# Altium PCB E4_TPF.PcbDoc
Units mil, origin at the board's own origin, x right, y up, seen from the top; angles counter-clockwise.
Board outline 7890 x 4000 mil, 2 copper layers (Top Layer, Bottom Layer); 83 components, 46 nets, 240 pads, 24 vias.
Unrouted connection lines stored in the file: 2.
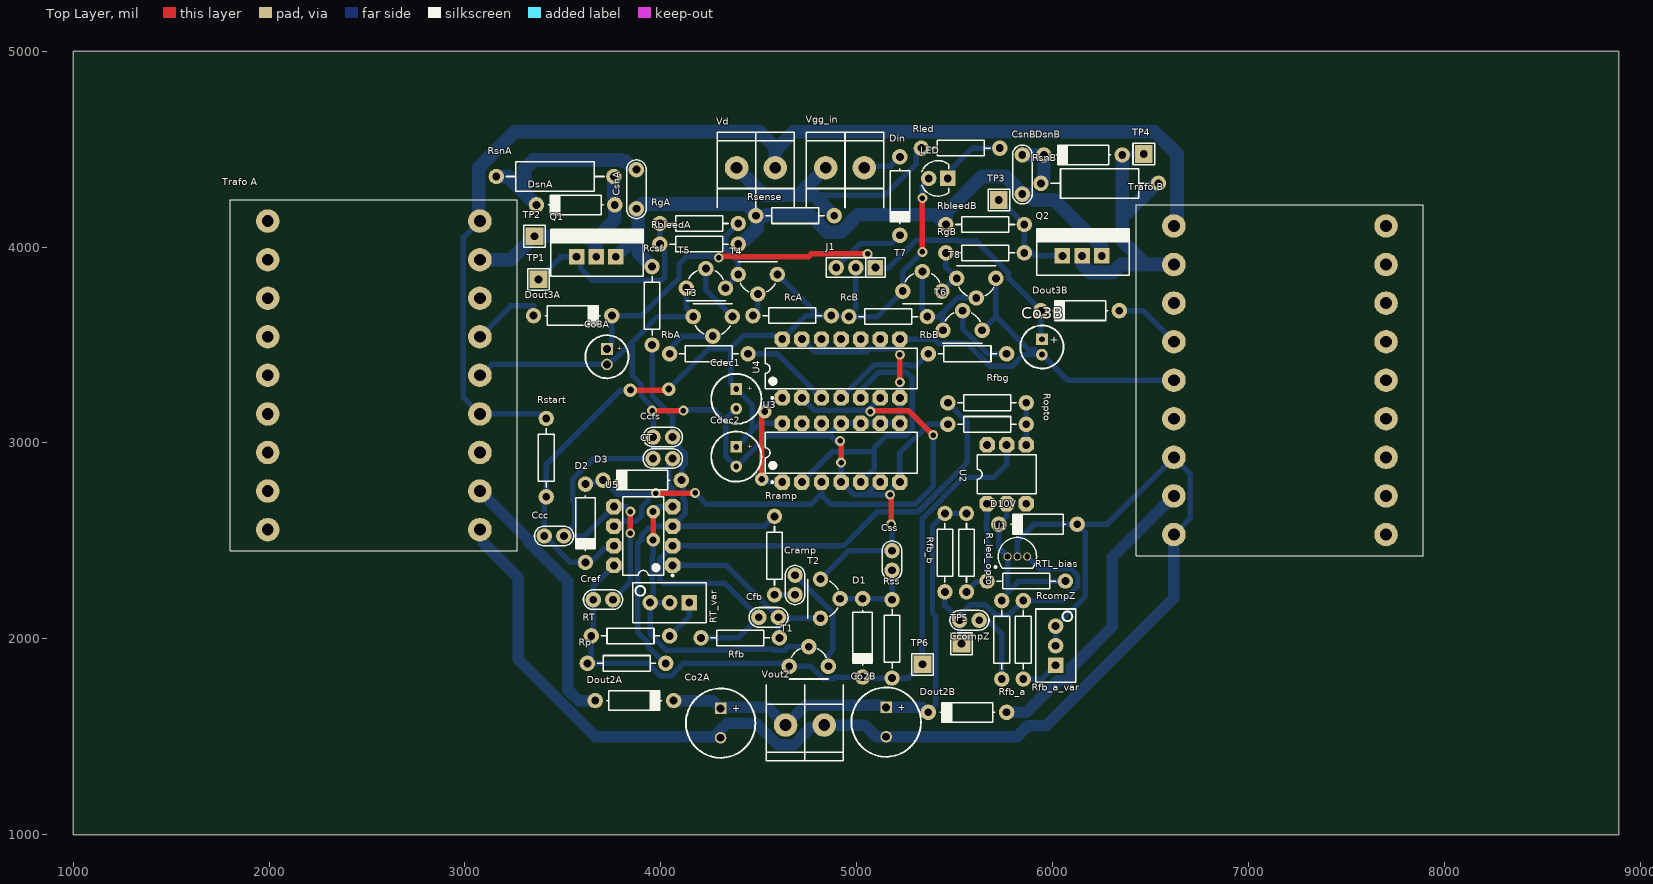
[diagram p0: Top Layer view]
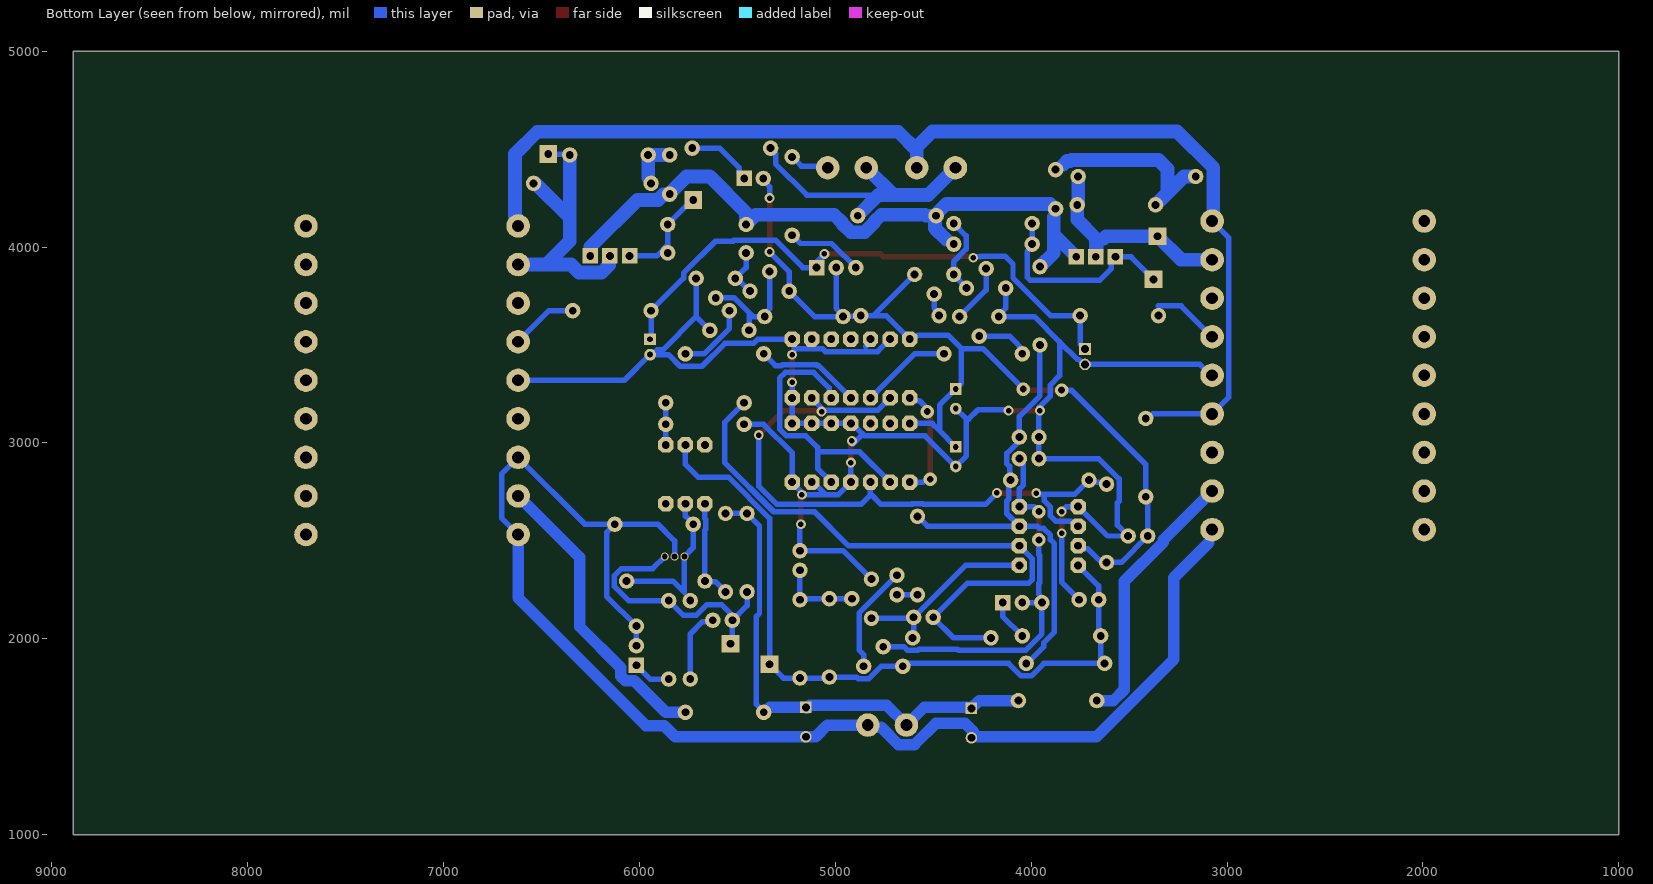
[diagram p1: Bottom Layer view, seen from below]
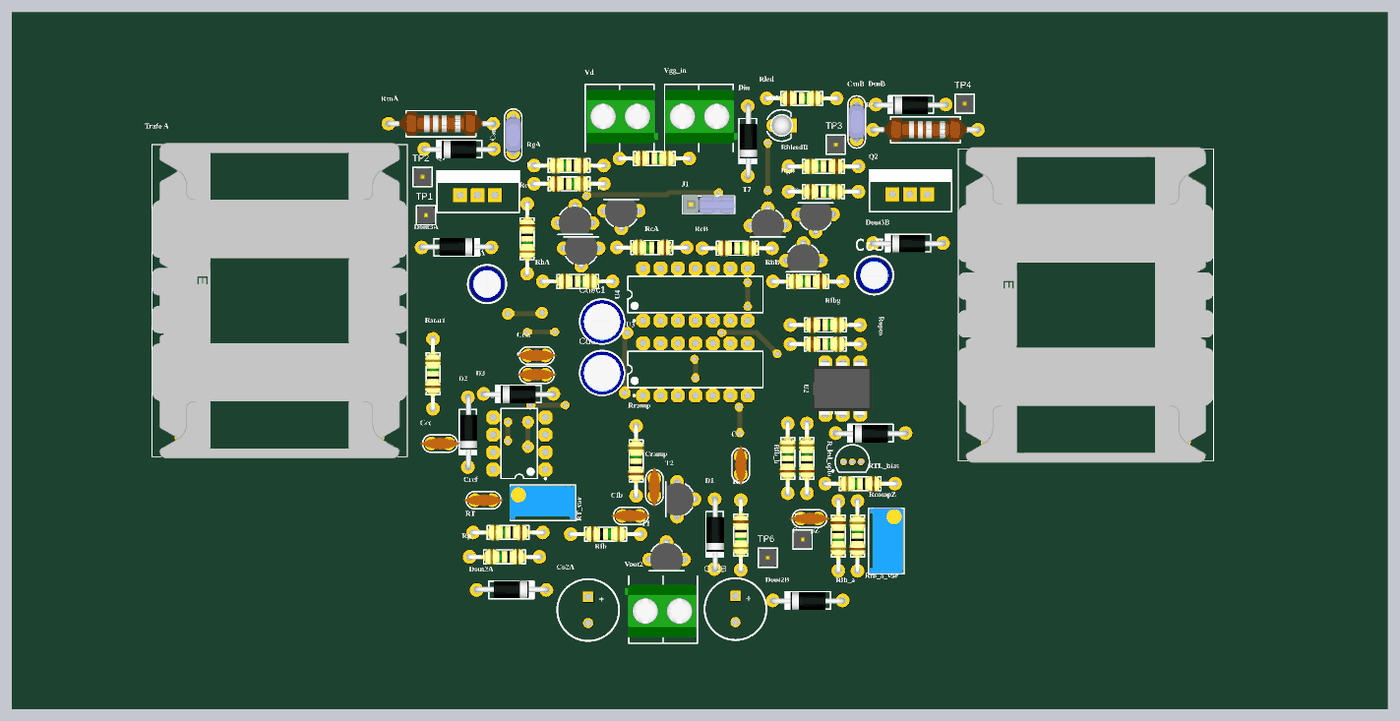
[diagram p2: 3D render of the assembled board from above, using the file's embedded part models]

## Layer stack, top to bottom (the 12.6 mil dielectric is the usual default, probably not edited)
Top Solder: solder mask 0.4, Solder Resist, Dk 3.5
Top Layer: signal copper 1.4
Dielectric 1: dielectric 12.6, FR-4, Dk 4.8
Bottom Layer: signal copper 1.4
Bottom Solder: solder mask 0.4, Solder Resist, Dk 3.5

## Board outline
1000,1000 8890,1000 8890,5000 1000,5000

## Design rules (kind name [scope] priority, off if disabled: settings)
Clearance [All] p1: gap=10 ignorepadtopadclearanceinfootprint=FALSE except(0: Arc-Hole Track-Hole SMDPad-Hole THPad-Hole Via-Hole Fill-Hole Poly-Hole Region-Hole Text-Hole)
PolygonConnect [All] p1: connectstyle=Relief reliefconductorwidth=10 reliefentries=4 polygonreliefangle="90 Angle" airgapwidth=10
RoutingVias [All] p1: holewidth=28 width=50 viastyle="Through Hole" minholewidth=28 minwidth=50 maxholewidth=28 maxwidth=50
SolderMaskExpansion [All] p1: expansion=4 istentingtop=FALSE
Width [All] p1: maxlimit=70 minlimit=28 preferedwidth=28
30 further rules are at their usual default settings.

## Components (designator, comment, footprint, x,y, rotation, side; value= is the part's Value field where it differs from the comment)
Ccc "100n" CAP100 3455,2525 r180 top
Ccfs "100p" CAP100 4010,3030 r0 top
CcompZ "100p" CAP100 5575,2095 r180 top
Cdec1 "10u" CAP100RP2 4385,3225 r270 top
Cdec2 "10u" CAP100RP2 4385,2930 r270 top
Cfb "100p" CAP100 4550,2110 r0 top
Co2A "100u" CAP300RP 4305,1570 r270 top
Co2B "100u" CAP300RP 5150,1575 r270 top
Co3A "1u" CAP100RP#1 3725,3440 r270 top
Co3B "1u" CAP100RP#2 5945,3490 r270 top
Cramp "1n" CAP100 4685,2275 r270 top
Cref "100n" CAP100 3705,2200 r180 top
CsnA "680p" CAP200 3875,4295 r90 top
CsnB "680p" CAP200 5845,4370 r90 top
Css "10u" CAP100 5180,2400 r270 top
CT "1.5n" CAP100 4010,2920 r0 top
D1 "1N4148" DO41 5030,2005 r270 top
D2 "1N5817" DO41 3615,2590 r270 top
D3 "1N5817" DO41 3905,2810 r180 top
D10V "BZX84C10L" DO41 5925,2585 r180 top
Din "1N4001" DO41 5220,4260 r270 top
Dout2A "MUR460" DO41 3865,1685 r0 top
Dout2B "MUR460" DO41 5565,1625 r180 top
Dout3A "MUR110" DO41 3550,3650 r0 top
Dout3B "MUR110" DO41 6140,3675 r180 top
DsnA "1N5819" DO41 3565,4215 r180 top
DsnB "1N5819" DO41 6155,4470 r180 top
J1 "JUMPER" JUMPER3 4995,3895 r180 top
LED "LED" LED3 5415,4350 r0 top
Q1 "IRF540" "TO-220 V" 3670,3950 r0 top
Q2 "IRF540" "TO-220 V" 6150,3955 r0 top
R_led_opto "15k" RES400 5560,2240 r90 top
RbA "1k" RES400 4045,3455 r0 top
RbB "1k" RES400 5765,3455 r180 top
RbleedA "10k" RES400 3995,4015 r0 top
RbleedB "10k" RES400 5855,4115 r180 top
RcA "560" RES400 4870,3650 r180 top
RcB "560" RES400 4960,3645 r0 top
RcompZ "88.7k" RES400 5740,2195 r270 top
Rcsf "1k" RES400 3955,3900 r270 top
Rfb "1.8k" RES400 4205,2005 r0 top
Rfb_a "1.8k" RES400 5850,1795 r90 top
Rfb_a_var "100" "PRESET V" 6015,1965 r90 top
Rfb_b "82k" RES400 5450,2240 r90 top
Rfbg "4.7k" RES400 5465,3205 r0 top
RgA "33" RES400 4395,4120 r180 top
RgB "33" RES400 5455,3970 r0 top
Rled "1.5k" RES400 5330,4505 r0 top
Ropto "1k" RES400 5465,3095 r0 top
Rp "12k" RES400 4025,1875 r180 top
Rramp "100k" RES400 4580,2225 r90 top
Rsense "0.1" RES400 4485,4160 r0 top
RsnA "220" RES600 3160,4360 r0 top
RsnB "220" RES600 5940,4325 r0 top
Rss "47k" RES400 5180,2200 r270 top
Rstart "100k" RES400 3415,2725 r90 top
RT "5.6k" RES400 4045,2015 r180 top
RT_var "5k" "PRESET V" 4045,2185 r180 top
RTL_bias "1k" RES400 6065,2295 r180 top
T1 "BC547B" TO92 4755,1910 r180 top
T2 "BC557B" TO92 4865,2205 r90 top
T3 "BC547B" TO92 4265,3595 r0 top
T4 "2N2222" TO92 4495,3810 r0 top
T5 "2N2905A" TO92 4230,3840 r180 top
T6 "BC547B" TO92 5540,3625 r180 top
T7 "2N2222" TO92 5335,3825 r180 top
T8 "2N2905A" TO92 5610,3790 r0 top
TP1 "TP" TPTH 3375,3835 r0 top
TP2 "TP" TPTH 3355,4055 r0 top
TP3 "TP" TPTH 5725,4240 r270 top
TP4 "TP" TPTH 6465,4475 r0 top
TP5 "TP" TPTH 5535,1975 r0 top
TP6 "TP" TPTH 5335,1870 r0 top
"Trafo A" "B66243B1018T001" B66243B1018T001 2535,3345 r270 top
"Trafo B" "B66243B1018T001" B66243B1018T001 7160,3320 r270 top
U1 "TL431ACZ" TO-92 5820,2420 r270 top
U2 "4N25" DIP6 5665,2690 r90 top
U3 "CD4013BE" N0014A 4920,2950 r90 top
U4 "CD4011BE" N0014A 4920,3380 r90 top
U5 "UC3843AN" P0008A 3910,2525 r180 top
Vd "BORNERA 2" BORNERA2 4485,4405 r270 top
Vgg_in "BORNERA 2" BORNERA2 4940,4405 r270 top
Vout2 "BORNERA 2" BORNERA2 4735,1560 r90 top

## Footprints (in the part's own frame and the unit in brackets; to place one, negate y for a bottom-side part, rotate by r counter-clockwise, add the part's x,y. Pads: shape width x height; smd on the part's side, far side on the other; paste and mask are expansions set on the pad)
B66243B1018T001 [mil]
  round 120 hole 60: 1(-787.4,-541.34) 2(-787.4,541.34) 3(-590.55,-541.34) 4(-590.55,541.34) 5(-393.7,-541.34) 6(-393.7,541.34) 7(-196.85,-541.34) 8(-196.85,541.34) 9(0,-541.34) 10(0,541.34) 11(196.85,-541.34) 12(196.85,541.34) 13(393.7,-541.34) 14(393.7,541.34) 15(590.55,-541.34) 16(590.55,541.34) 17(787.4,-541.34) 18(787.4,541.34)
  silkscreen extent -896,-732 896,732, body extent -906,-732 906,732, height 1795
BORNERA2 [mil] "Bornera con Tornillos 5mm separación"
  round 120 hole 60: 1(0,98.43) 2(0,-98.43)
  silkscreen extent -181,-197 205,197, body extent -148,-193 155,221, height 394
CAP100 [mil]
  oval 79.06x79 hole 40: 1(-50,0) 2(50,0)
  silkscreen extent -100,-50 100,50, body extent -115,-33 115,34, height 241
CAP100RP#1 [mil] "Body diameter 5mm"
  rect 59x59 hole 40: 1(-39.37,0)
  round 59 hole 40: 2(39.37,0)
  silkscreen extent -110,-110 110,110, body extent -99,-99 99,100, height 454
CAP100RP#2 [mil] "Body diameter 5mm"
  rect 60x60 hole 30: 1(-39.37,0)
  round 60 hole 30: 2(39.37,0)
  silkscreen extent -110,-110 110,110, body extent -99,-99 99,100, height 454
CAP100RP2 [mil] "Body diameter 6.5mm"
  rect 60x60 hole 30: 1(-50,0)
  round 60 hole 30: 2(50,0)
  silkscreen extent -128,-128 128,128, body extent -124,-125 126,125, height 454
CAP200 [mil]
  oval 79.06x79 hole 40: 1(-100,0) 2(100,0)
  silkscreen extent -150,-50 150,50, body extent -110,-46 110,44, height 246
CAP300RP [mm]
  rect 1.5x1.5 hole 1.016: 1(-1.905,0)
  round 1.5 hole 1.016: 2(1.905,0)
  silkscreen extent -4.5,-4.5 4.5,4.5
DIP6 [mil]
  oct 79.06x79 hole 40: 1(0,0) 2(0,-100) 3(0,-200) 4(300,-200) 5(300,-100) 6(300,0)
  silkscreen extent 50,-250 250,50, body extent -5,-269 305,77, height 209
DO41 [mil]
  oval 79.06x79 hole 40: 1(-200,0) 2(200,0)
  silkscreen extent -140,-50 140,50, body extent -215,-47 215,54, height 80
JUMPER3 [mil]
  rect 79.06x79 hole 40: 1(-100,0)
  oval 79.06x79 hole 40: 2(0,0) 3(100,0)
  silkscreen extent -150,-50 150,50, body extent -150,-51 150,50, height 636
LED3 [mil]
  oval 79.06x79 hole 40: 1(-48,0)
  rect 79.06x79 hole 40: 2(49,0)
  silkscreen extent -84,-90 54,90, body extent -65,-64 65,65, height 19
N0014A [mil] "DIP, 14-Leads, Body 19.7x6.6mm, Pitch 2.54mm"
  oct 79.06x79 hole 40: 1(-150,300) 2(-150,200) 3(-150,100) 4(-150,0) 5(-150,-100) 6(-150,-200) 7(-150,-300) 8(150,-300) 9(150,-200) 10(150,-100) 11(150,0) 12(150,100) 13(150,200) 14(150,300)
  silkscreen extent -155,-388 104,388, body extent -155,-388 155,388, height 200
P0008A [mil] "DIP, 8-Leads, Body 10.15x6.6mm, Pitch 2.54mm"
  oct 79.06x79 hole 40: 1(-150,150) 2(-150,50) 3(-150,-50) 4(-150,-150) 5(150,-150) 6(150,-50) 7(150,50) 8(150,150)
  silkscreen extent -155,-201 104,206, body extent -155,-200 155,200, height 200
"PRESET V" [mil]
  rect 79.06x79 hole 40: 1(-100,0)
  oval 79.06x79 hole 40: 2(0,0) 3(100,0)
  silkscreen extent -188,-102 188,102, body extent -185,-95 190,95, height 455
RES400 [mil]
  oval 79.06x79 hole 40: 1(0,0) 2(400,0)
  silkscreen extent 50,-40 350,40, body extent -12,-45 412,46, height 96
RES600 [mil]
  oval 79.06x79 hole 40: 1(0,0) 2(600,0)
  silkscreen extent 50,-75 550,75, body extent -16,-68 616,70, height 141
TO92 [mil]
  oval 79.06x79 hole 40: 1(0,-50) 2(100,50) 3(-100,50)
  silkscreen extent -100,-39 100,115, body extent -110,-61 110,110, height 315
TO-92 [mil] "TO, Flat Index; 3 In-Line, Axial Leads; Body Dia. 4.7mm; Lead Dia. 0.56 mm (max)"
  round 41 hole 30: 1(0,-50) 2(0,0) 3(0,50)
  silkscreen extent -98,-116 59,98, body extent -98,-98 59,98, height 195
"TO-220 V" [mil]
  rect 79.06x79 hole 40: 1(-100,0) 2(0,0) 3(100,0)
  silkscreen extent -232,-100 240,139, body extent -197,-79 197,118, height 709
TPTH [mm]
  rect 2.3x2.3 hole 1.016: 1(0,0)
  silkscreen extent -1.4,-1.4 1.4,1.4, body extent -1.27,-1.27 1.27,1.27, height 6.04

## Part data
Ccc Ccfs CcompZ Cfb Cramp Cref CsnA CsnB Css CT: library part CAP
Cdec1 Cdec2 Co2A Co2B Co3A Co3B: library part CAPPOL
D1 Din Dout2A Dout2B Dout3A Dout3B: library part DIODO
D2 D3 D10V: library part "DIODO ZENER"
DsnA DsnB: library part "DIODO SCHOTTKY"
J1: library part JUMPER3
Q1 Q2: library part "MOSFET N"
R_led_opto RbA RbB RbleedA RbleedB RcA RcB RcompZ Rcsf Rfb Rfb_a Rfb_b Rfbg RgA RgB Rled Ropto Rp Rramp Rsense RsnA RsnB Rss Rstart RT RTL_bias: library part RES
Rfb_a_var RT_var: library part PRESET
T1 T3 T4 T6 T7: library part "TRANSISTOR NPN"
T2 T5 T8: library part "TRANSISTOR PNP"
"Trafo A" "Trafo B": "Inductor", Manufacturer_Name=TDK, Mouser Part Number=N/A
U1: library part CMP-0242-00006-1, "Programmable Voltage Reference, 2.5 to 36V, 3-Pin TO-92"
U3: library part CMP-1619-00744-2, "CMOS Dual D-Type Flip Flop, N0014A, TUBE", F @ Nom Voltage(Max)(Mhz)=8, Generic Part Number=CD4013B, ICC @ Nom Voltage(Max)(mA)=0.06, Manufacturer="Texas Instruments", Operating Temperature Range(C)="-55 to 125", Rating=Military, tpd @ Nom Voltage(Max)(ns)=130, Voltage(Nom)(V)=10
U4: library part CMP-1627-00488-2, "CMOS Quad 2-Input NAND Gate, N0014A, TUBE", F @ Nom Voltage(Max)(Mhz)=8, Generic Part Number=CD4011B, ICC @ Nom Voltage(Max)(mA)=0.015, Manufacturer="Texas Instruments", Operating Temperature Range(C)="-55 to 125", Rating=Military, Voltage(Nom)(V)=10
U5: library part CMP-0319-00327-2, "PWM Controller with Current Control, 100 % Duty Cycle, 0 to +70 degC, 8-pin PDIP (P), Green (RoHS & no Sb/Br)", Frequency(Max)(kHz)=450, Manufacturer="Texas Instruments", Rating=Catalog

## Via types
v1: diameter 50, hole 28, Top Layer to Bottom Layer, 18 vias
v2: diameter 69, hole 35, Top Layer to Bottom Layer, 6 vias

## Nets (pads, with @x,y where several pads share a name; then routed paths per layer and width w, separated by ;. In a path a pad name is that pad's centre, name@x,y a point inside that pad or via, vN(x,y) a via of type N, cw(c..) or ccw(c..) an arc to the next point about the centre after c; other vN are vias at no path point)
-Q: U3.2 U3.5 U4.5 | length 1486.3
  Bottom Layer w28: U3.2 4875,2955 5090.31,2955 ; U3.5 5090.31,2870.31 5090.31,2955 ; U4.5 5031.34,3241.34 5031.34,3281.34 5110,3360 5255,3360 5283.5,3331.5 5283.5,3070.28 5249.69,3036.47 5149.69,3036.47 5090.31,2977.09 5090.31,2955
GND: "Trafo A.10" "Trafo B.9" Ccc.1 Ccfs.1 Cdec1.2 Cdec2.2 Co3A.2 Co3B.2 Cref.1 Css.1 CT.1 Rled.1 Ropto.1 Rsense.2 T2.2 T3.3 T5.2 T6.3 T8.2 U3.4 U3.6 U3.7 U3.8 U3.9 U3.10 U3.11 U4.7 U4.8 U4.9 U4.12 U4.13 U5.5 Vd.2 Vgg_in.2 | length 11891.7
  Top Layer w28: v1(3844.24,2539.24) 3844.24,2649.24 v1(3845,2650) ; v1(3955,3165) v1(4115,3165) ; v1(4915,3010) 4915,3004.05 4920,2999.05 v1(4920,2900) ; v1(5170,2735.77) 5170,2729.82 5175,2724.82 v1(5175,2585) ; v1(5220,3310) v1(5220,3450)
  Bottom Layer w28: 3076.34,3345 3083.11,3345 3138.74,3400.63 Co3A.2 3731.66,3400.63 3756.9,3425.87 3764.44,3425.87 3854.29,3515.71 ; Cref.1 3843.47,2288.47 3843.47,2538.47 v1(3844.24,2539.24) v1@3845,2540 ; v1(3845,2650) 3821.34,2673.66 3761.34,2673.66 U5.5 3610,2525 Ccc.1 3560,2580 3560,2693.91 3551.5,2702.41 3551.5,2816.33 3655.17,2920 CT.1 Ccfs.1 3960,3181.26 3903.5,3237.76 3903.5,3294.23 3854.29,3343.45 3854.29,3515.71 ; v1@4114.67,3170 4115.46,3169.21 4134.77,3169.21 4135.56,3170 4270,3170 4319,3121 4331,3121 ; T5.2 4130,3686.9 4165,3651.9 T3.3 3983.57,3645 3854.29,3515.71 ; Cdec1.2 4331,3121 ; 4510,4281.4 4510,4281.57 ; U4.13 4783.53,3466.47 5049.69,3466.47 5063.22,3480 5120,3480 ; 4780,4265 5015,4265 5144.53,4265 5304.5,4424.97 Rled.1@5304.5,4477.09 ; T2.2 4960,2450 Css.1 v1@5180,2595 ; U4.12 4820,3518.42 4843.84,3494.59 4843.84,3491.16 4845,3490 ; 4859.11,3045.89 v1@4912,2993 ; v1(4920,2900) U3.4 4983.53,2736.47 5049.69,2736.47 ; U3.6 5113.22,2800 5049.69,2736.47 ; U4.9 5120,3480 ; v1@5220,3300 U4.7 U3.8 U3.9 U3.10 U3.11 4913.22,3100 4849.69,3036.47 4541.47,3036.47 Cdec2.2 4331,2934 4331,3121 ; v1@5220,3460 5208.6,3471.4 5208.6,3480 ; Rled.1@5325.4,4505 Rled.1 ; Ropto.1 5365,3095 5220,2950 U3.7 5220,2797.07 5174.21,2751.28 5174.21,2739.98 v1(5170,2735.77) 5169.3,2736.47 5049.69,2736.47 ; T6.3 5710,3645 ; T8.2 5710,3645 ; 6618.66,3320 6075.63,3320 Co3B.2 Co3B.2@5936.34,3450.63 ; 5120,3480 5208.6,3480 ; 5208.6,3480 5208.6,3518.6 U4.8 5395.17,3530 5416.96,3508.21 5563.21,3508.21 5679.93,3391.5 5791.33,3391.5 5850.46,3450.63 Co3B.2@5936.34,3450.63 ; 5710,3645 5879.63,3475.37 5909.63,3475.37 5918.37,3466.63 5920.34,3466.63 Co3B.2@5936.34,3450.63
  Bottom Layer w70: Vd.2 4510,4281.57 ; 4510,4281.4 4526.4,4265 4701.57,4265 ; Vgg_in.2 4701.57,4265 ; Rsense.2 4780,4265 4701.57,4265 ; Rled.1@5330,4502.59 Rled.1
GND_OUT: "Trafo A.18" "Trafo B.13" "Trafo B.17" Co2A.2 Co2B.2 D10V.1 Rfb_a_var.2 Rfb_a_var.3 U1.2 Vout2.2 | length 7267
  Bottom Layer w28: 3076.34,2557.6 3093.94,2539.99 3093.94,2491.06 ; Co2B.2 5155.94,1505.94 5165,1505.94 5180.94,1505.94 ; U1.2 5820,2500 5905,2585 D10V.1 ; Rfb_a_var.2 Rfb_a_var.3 6166.53,2216.53 6166.53,2543.1 6125,2584.63 D10V.1 ; 6618.66,2532.6 6702.66,2616.6 6702.66,2842.3 6618.66,2926.3 6277.36,2585 D10V.1
  Bottom Layer w59: 3093.94,2491.06 3272.5,2312.5 3272.5,1894.92 3666.45,1500.97 4275.89,1500.97 4287.46,1512.54 4299.03,1524.11 4299.03,1531.45 4337.57,1569.99 4379.99,1569.99 4485.86,1570 4595.36,1460.5 4677.79,1460.5 4765.62,1548.33 4821.75,1548.33 Vout2.2 5040,1560 5099.99,1500.01 Co2B.2 5180.94,1500 5816.71,1500 5872.71,1556 5966,1556 6618.66,2208.66 6618.66,2532.6
NetCcfs_2: Ccfs.2 D3.1 Rcsf.2 Rp.1 Rramp.2 U5.3 | length 2478.1
  Bottom Layer w28: Rcsf.2 3955,3240 4060,3135 Ccfs.2 4069.79,3020.21 4069.79,3000.04 4123.53,2946.3 4123.53,2893.7 4110,2880.17 4110,2815 D3.1 4114.79,2800.21 4114.79,2768.31 4115,2768.1 4115,2713.22 4123.53,2704.69 4123.53,2638.53 U5.3 ; Rp.1@4022.5,1872.5 3935,1960 3935,1981.43 3881.47,2034.96 3881.47,2486.47 3901.5,2506.5 3901.5,2529.23 3935.77,2563.5 3958.5,2563.5 3970,2575 U5.3 ; Rramp.2 4530,2575 U5.3
NetCcompZ_1: CcompZ.1 RcompZ.2 | length 374
  Bottom Layer w28: CcompZ.1 5632.14,2087.86 5677.14,2087.86 5740,2025 RcompZ.2
NetCcompZ_2: CcompZ.2 Rfb_a.2 Rfb_b.1 TP5.1 U1.3 | length 1387.9
  Bottom Layer w28: Rfb_b.1 5450,2170 CcompZ.2 ; TP5.1 5525,1985 CcompZ.2 ; U1.3 5931.5,2358.5 6091.33,2358.5 6128.53,2321.3 6128.53,2268.7 6054.83,2195 Rfb_a.2 5775,2120 5710,2120 5655,2175 5580,2175 5534.79,2129.79 5534.79,2104.79 CcompZ.2
NetCfb_2: Cfb.2 Rfb.2 T2.3 U5.1 | length 973.9
  Bottom Layer w28: U5.1 4335,2375 Cfb.2 ; Rfb.2 4600,2010 Cfb.2 ; T2.3 4605,2105 Cfb.2
NetCramp_1: Cramp.1 T1.3 | length 554.9
  Bottom Layer w28: Cramp.1 4878.5,2131.5 4878.5,1943.5 4855,1920 T1.3
NetCramp_2: Cramp.2 Rramp.1 | length 105
  Bottom Layer w28: Rramp.1 Cramp.2
NetCsnA_2: CsnA.2 DsnA.2 RsnA.1 | length 997.8
  Bottom Layer w28: 3817.33,4438.9 3820.83,4435.4 ; 3836.23,4420 3861.23,4395 CsnA.2
  Bottom Layer w70: RsnA.1 3220,4360 3303.77,4276.23 ; DsnA.2 3303.77,4276.23 ; 3817.33,4438.9 3800.63,4438.9 3795.03,4444.5 3350.38,4444.5 3303.77,4397.89 3303.77,4276.23 ; 3820.83,4435.4 3836.23,4420
NetCsnB_2: CsnB.2 DsnB.2 RsnB.1 | length 272.9
  Bottom Layer w28: CsnB.2@5836.73,4461.73 CsnB.2 ; RsnB.1 5940,4338.77 RsnB.1@5955,4353.77
  Bottom Layer w70: CsnB.2 DsnB.2 RsnB.1@5955,4353.77
NetCss_2: Css.2 D1.1 Rss.1 T2.1 | length 417.1
  Bottom Layer w28: T2.1 D1.1 5175,2205 Rss.1 Css.2
NetCT_2: CT.2 RT_var.2 RT_var.3 T1.1 U5.4 | length 1961.6
  Top Layer w28: v2(3960,2505) v2(3960,2650)
  Bottom Layer w28: v2(3960,2505) 3960,2428.74 3957,2425.74 3957,2285.66 3960,2282.66 3960,2226.9 3954.79,2221.69 3954.79,2194.79 RT_var.3 ; v2(3960,2650) 3985,2675 U5.4 4060,2765.17 4041.47,2783.7 4041.47,2887.7 4060,2906.23 CT.2 ; RT_var.2 RT_var.3 ; T1.1 4649.83,1960 4631.33,1941.5 4578.67,1941.5 4572.53,1947.64 4376.09,1947.64 4369.94,1941.5 4028.67,1941.5 3945,2025.17 RT_var.3
NetD10V_2: D10V.2 RcompZ.1 RTL_bias.1 U1.1 U2.2 | length 807.3
  Bottom Layer w28: U2.2 5765,2626.9 5725,2586.9 D10V.2 5725,2465 U1.1 5770,2236.93 5828.07,2295 RTL_bias.1
NetDin_1: Din.1 Vgg_in.1 | length 205.3
  Bottom Layer w28: Vgg_in.1 5046.76,4413.34 5173.34,4413.34 Din.1@5220.68,4460.68
NetDin_2: Din.2 J1.3 | length 421.2
  Bottom Layer w28: J1.3@4887.32,3887.32 5018,4018 5178,4018 Din.2 5220,4069.93 Din.2@5215.04,4064.96
NetDout2A_1: "Trafo A.16" Dout2A.1 | length 1363.1
  Bottom Layer w59: 3076.34,2754.45 3325.97,2504.81 3325.97,2492.28 3525,2293.25 3525,1740 3580,1685 Dout2A.1
NetDout2B_1: "Trafo B.15" Dout2B.1 | length 1542.9
  Bottom Layer w59: Dout2B.1 5865,1625 6025.97,1785.97 6070.86,1785.97 6094,1809.11 6094,1851.71 6305,2062.71 6305,2415.79 6618.66,2729.45
NetDout3A_1: "Trafo A.8" Dout3A.1 | length 339.2
  Bottom Layer w28: 3076.34,3541.85 3234.49,3700 3350,3700
NetDout3B_1: "Trafo B.7" Dout3B.1 | length 344.2
  Bottom Layer w28: Dout3B.1 6460.51,3675 6618.66,3516.85
NetDsnA_1: "Trafo A.4" DsnA.1 Q1.2 RsnA.2 TP2.1 | length 1153.7
  Bottom Layer w28: 3630,4042.46 3644.47,4027.99 Q1.2@3644.47,3975.5 ; DsnA.1@3760,4220 DsnA.1
  Bottom Layer w70: 3076.34,3935.55 3235.55,3935.55 TP2.1 3617.46,4055 3630,4042.46 ; Q1.2 Q1.2@3670,3975.5 ; Q1.2@3670,3954.5 3670,4045 3765,4140 DsnA.1 ; DsnA.1@3760,4220 RsnA.2
NetDsnB_1: "Trafo B.3" DsnB.1 Q2.2 RsnB.2 TP4.1 | length 1538.1
  Bottom Layer w28: DsnB.1 6358.04,4473.04 6463.04,4473.04 TP4.1 TP4.1@6455,4485 ; RsnB.2@6530,4325 RsnB.2
  Bottom Layer w70: Q2.2 6154.53,3950.5 6154.53,3907.81 6191.83,3870.5 6308.17,3870.5 6348.22,3910.55 6475,3910.55 ; DsnB.1 6355,4150 ; RsnB.2@6530,4325 6355,4150 ; 6618.66,3910.55 6475,3910.55 ; 6355,4150 6355,4030.55 6475,3910.55
NetLED_2: LED.2 Rled.2 | length 347.2
  Bottom Layer w28: LED.2 5489.53,4375.5 5489.53,4404.53 5590,4505 Rled.2
NetQ1_1: Q1.1 RbleedA.1 RgA.2 TP1.1 | length 1056.5
  Bottom Layer w28: TP1.1 3490,3950 Q1.1 3591.21,3928.79 3591.21,3888.79 3650,3830 4003.6,3830 4020,3846.4 4020,3976.23 3995,4001.23 RgA.2
NetQ2_1: Q2.1 RbleedB.1 RgB.2 TP3.1 | length 518.3
  Bottom Layer w28: TP3.1 5756.28,4208.72 5761.28,4208.72 RbleedB.1 5855,4010 5910,3955 Q2.1 ; RgB.2@5855,3956.23 RgB.2
NetR_led_opto_1: R_led_opto.1 RTL_bias.2 U2.1 | length 525.7
  Bottom Layer w28: R_led_opto.1 5611.73,2291.73 5661.73,2291.73 RTL_bias.2 5665,2555.17 5661.47,2558.7 5661.47,2611.3 5665,2614.83 U2.1
NetRbA_1: RbA.1 T3.1 | length 282.3
  Bottom Layer w28: RbA.1@4020,3455 4110,3545 T3.1
NetRbA_2: RbA.2 U4.3 | length 493.2
  Bottom Layer w28: RbA.2@4420,3455 4595,3455 U4.3
NetRbB_1: RbB.1 T6.1 | length 368.7
  Bottom Layer w28: T6.1 5540,3585.17 5670.17,3455 RbB.1
NetRbB_2: RbB.2 U4.4 | length 540.7
  Bottom Layer w28: U4.4 5085,3395 5091.26,3395 5094.26,3398 5270.74,3398 5273.74,3395 5305,3395 RbB.2
NetRcA_2: RcA.2 T3.2 T4.1 T5.1 | length 421.3
  Bottom Layer w28: T5.1 4230,3780 T3.2 ; RcA.2 4470,3663.77 4495,3688.77 T4.1
NetRcB_2: RcB.2 T6.2 T7.1 T8.1 | length 619.5
  Bottom Layer w28: T7.1 5335,3683.77 5360,3658.77 RcB.2 5420.17,3645 5440,3664.83 ; T6.2 5440,3664.83 ; T8.1 5515.17,3740 5440,3664.83
NetRfb_a_1: Rfb_a.1 Rfb_a_var.1 | length 194
  Bottom Layer w28: Rfb_a.1 5945,1795 Rfb_a_var.1@5989.47,1839.47 ; Rfb_a_var.1@5989.5,1839.47 Rfb_a_var.1
NetRfbg_2: Rfbg.2 Ropto.2 U2.4 | length 215
  Bottom Layer w28: U2.4 Ropto.2 Rfbg.2
NetRT_1: RT.1 RT_var.1 | length 211.4
  Bottom Layer w28: RT.1 4145,2115 RT_var.1
Q: U3.1 U4.1 | length 594.1
  Top Layer w28: v2(4515,2815) 4515,3139.05 4530,3154.05 v2(4530,3160)
  Bottom Layer w28: v2@4515,2835 4550,2800 U3.1 ; v2@4522.5,3167.5 4571.16,3216.16 4606.16,3216.16 U4.1
Vcontrol: D2.1 D3.2 U3.3 U4.2 U4.6 U5.6 | length 3336.9
  Top Layer w28: v1(3974.25,2744.25) 4174.25,2744.25 v1(4175,2745) ; v1(5070,3160) 5073.53,3163.53 5266.47,3163.53 v1(5390,3040)
  Bottom Layer w28: D2.1@3640,2790 3649.79,2799.79 3680.96,2799.79 3691.17,2810 D3.2 3776.5,2738.5 3921.5,2738.5 ; U5.6 3771.58,2575 3797.58,2601 3874.6,2601 3901.5,2627.9 3901.5,2674.23 3932.04,2704.77 3932.04,2727.96 3921.5,2738.5 ; v1(3974.25,2744.25) 3968.5,2738.5 3921.5,2738.5 ; v1(4175,2745) 4233.23,2686.77 4551.94,2686.77 4553.7,2688.53 4606.3,2688.53 4608.06,2686.77 4766.77,2686.77 4818.66,2738.66 ; U4.2 4783.53,3166.47 5056.47,3166.47 U4.6 ; U3.3 4820,2735 4868.23,2686.77 5298.03,2686.77 5390,2778.74 v1(5390,3040)
Vd: "Trafo A.2" "Trafo A.12" "Trafo B.1" Rstart.2 Vd.1 | length 5918.7
  Bottom Layer w28: 3076.34,4132.4 2992.34,4048.4 2992.34,3232.15 3076.34,3148.15 3378.08,3148.15 3401.23,3125 Rstart.2 ; 4583.43,4493.43 4583.43,4511.57
  Bottom Layer w70: 3076.34,4132.4 3070,4138.74 3070,4405 3255,4590 4505,4590 4583.43,4511.57 ; Vd.1 4583.43,4493.43 4678.52,4588.53 6521.3,4588.53 6635,4474.83 6635,4159.1 6628.23,4152.32 6628.23,4116.97 6618.66,4107.4
VgA: RgA.1 T4.3 T5.3 | length 409.6
  Bottom Layer w28: T5.3 4330,3792.43 4395,3857.43 T4.3 4395,3925.17 4331.47,3988.7 4331.47,4056.47 RgA.1
VgB: RgB.1 T7.3 T8.3 | length 254.7
  Bottom Layer w28: T7.3 5437.43,3775 5502.43,3840 T8.3 5455,3895 RgB.1
Vgg: Ccc.2 Cdec1.1 Cdec2.1 D2.2 J1.2 LED.1 RcA.1 RcB.1 Rstart.1 T4.2 T7.2 U3.14 U4.14 U5.7 | length 4968.8
  Top Layer w28: v2(3845,3270) 4035,3270 v2(4040,3275) ; v1(5335,3975) v1(5335,4250)
  Bottom Layer w28: Rstart.1@3405,2739.82 3405.24,2739.58 3405.24,2701.41 3405,2701.17 Ccc.2 3540,2390 D2.2 ; Rstart.1 3415,2890 3793.91,3268.91 3843.91,3268.91 v2(3845,3270) ; D2.2@3640,2390 3711.16,2461.16 3746.16,2461.16 U5.7 ; v2@4025,3275 v2(4040,3275) 4246.3,3481.3 4356.47,3481.3 ; Cdec2.1 4467.5,3062.5 ; T4.2 4805,3650 ; U3.14 4505,3100 4467.5,3062.5 ; J1.2@4995,3899.72 4995,3686.9 4960,3651.9 RcB.1 ; v1(5335,3975) 5235,3875 T7.2 5105,3645 RcB.1 ; v1(5335,4250) 5335,4308.1 5367,4340.1 LED.1 ; 4356.47,3481.3 4356.47,3303.53 Cdec1.1 4467.5,3192.5 4467.5,3062.5 ; 4356.47,3481.3 4425.17,3550 4578.1,3550 4584.12,3543.98 4606.02,3543.98 U4.14 4740,3650 4805,3650 ; 4805,3650 RcA.1 4872.5,3647.5 4957.5,3647.5 RcB.1
Vo2: Co2A.1 Co2B.1 Dout2A.2 Dout2B.2 R_led_opto.2 Rfb_b.2 Vout2.1 | length 2583.9
  Bottom Layer w28: Dout2B.2 5365,1627.63 5404.28,1666.9 5404.28,2112.81 5386.5,2130.59 5386.5,2576.5 Rfb_b.2 R_led_opto.2
  Bottom Layer w59: Dout2A.2 4265,1685 Co2A.1 ; Co2A.1 Co2A.1 4322.36,1645.03 4327.34,1650 4546.57,1650 Vout2.1 4736.57,1660 5130,1660 Co2B.1@5145,1645 ; Co2B.1 5334.56,1650 5359.56,1625 Dout2B.2
Vo3: Co3A.1 Co3B.1 Dout3A.2 Dout3B.2 J1.1 | length 3010.3
  Top Layer w28: v1(4295,3945) 4299.21,3949.21 4314.77,3949.21 4319.06,3953.5 4366.67,3953.5 4368.67,3951.5 4755,3951.5 4768.5,3965 v1(5055,3965)
  Bottom Layer w28: Co3A.1 3750,3504.37 Dout3A.2 3900.17,3650 4092.59,3842.41 4092.59,3912.6 4133.49,3953.5 4256.33,3953.5 4260.62,3949.21 4290.79,3949.21 v1(4295,3945) ; v1(5055,3965) 5055,3959.05 5069.47,3944.57 5069.47,3920.5 J1.1 ; v1@5072.45,3947.55 5125,3895 5165,3895 5303.5,4033.5 5517.5,4033.5 5521,4030 5609.83,4030 5773.53,3866.3 5773.53,3841.47 Dout3B.2 5940,3534.37 Co3B.1
Vo_comp: Cfb.1 Rfb.1 Rfbg.1 U5.2 | length 3150.8
  Bottom Layer w28: Rfb.1 4395,2005 Cfb.1 4325,2285 4011.4,2285 3995,2301.4 3995,2410 U5.2 4931.26,2475 5105.03,2648.77 5313.77,2648.77 5565,2900 5565,3105 Rfbg.1
Vref: Cref.2 D1.2 Rp.2 Rss.2 RT.2 T1.2 TP6.1 U2.5 U5.8 | length 3769.9
  Bottom Layer w28: Rp.2 3935.17,1875 3998.67,1811.5 4051.33,1811.5 4114.83,1875 T1.2@4655,1875 ; Rp.2@3645,1865 RT.2 3645,2028.77 3655,2038.77 Cref.2 3655,2270 U5.8 ; T1.2 4765.17,1860 4828.67,1796.5 4881.33,1796.5 4889.83,1805 D1.2 5035,1800 Rss.2 5265,1800 TP6.1 5335,2614.83 5545.17,2825 5700,2825 5765,2890 U2.5
Vsense: CsnA.1 CsnB.1 Q1.3 Q2.3 RbleedA.2 RbleedB.2 Rcsf.1 Rsense.1 | length 3501.9
  Bottom Layer w28: Q1.3 Q1.3@3795.53,3975.5 ; CsnA.1 3884.76,4185.24 3884.76,4153.31 3885,4153.07 ; RbleedA.2 4408.83,4015 4430.97,4037.14 4432.14,4037.14 ; Rsense.1 Rsense.1@4490.21,4154.79 ; Rsense.1@4485,4168.07 4500,4153.07 4500,4150 Rsense.1@4509.76,4159.76 ; 4536.69,4159.76 4541.93,4165
  Bottom Layer w70: Q1.3@3795.53,3975.53 3885,4065 ; CsnA.1 3877.41,4195 3902.41,4220 4433.07,4220 4483.25,4169.82 4483.25,4164.16 Rsense.1@4485,4164.16 ; 3885,4153.07 3885,4065 ; Rcsf.1 3885,3970 3885,4065 ; 4432.14,4037.14 4490.21,4095.21 Rsense.1@4490.21,4154.79 ; Rsense.1@4509.76,4159.76 4536.69,4159.76 ; 4541.93,4165 4765,4165 4800.47,4129.53 4800.47,4125 4849.97,4075.5 4920.03,4075.5 4964.76,4120.24 4964.76,4124.93 5004.83,4165 5405,4165 RbleedB.2 5456.75,4116.75 5456.75,4176.75 5640,4360 5759.19,4360 5843.28,4275.91 5843.28,4271.72 CsnB.1 5846.75,4268.25 5877.22,4268.25 5904.97,4240.5 6009.5,4240.5 6250,4000
pads on no net: "Trafo A.1" "Trafo A.3" "Trafo A.5" "Trafo A.6" "Trafo A.7" "Trafo A.9" "Trafo A.11" "Trafo A.13" "Trafo A.14" "Trafo A.15" "Trafo A.17" "Trafo B.2" "Trafo B.4" "Trafo B.5" "Trafo B.6" "Trafo B.8" "Trafo B.10" "Trafo B.11" "Trafo B.12" "Trafo B.14" "Trafo B.16" "Trafo B.18" U2.3 U2.6 U3.12 U3.13 U4.10 U4.11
